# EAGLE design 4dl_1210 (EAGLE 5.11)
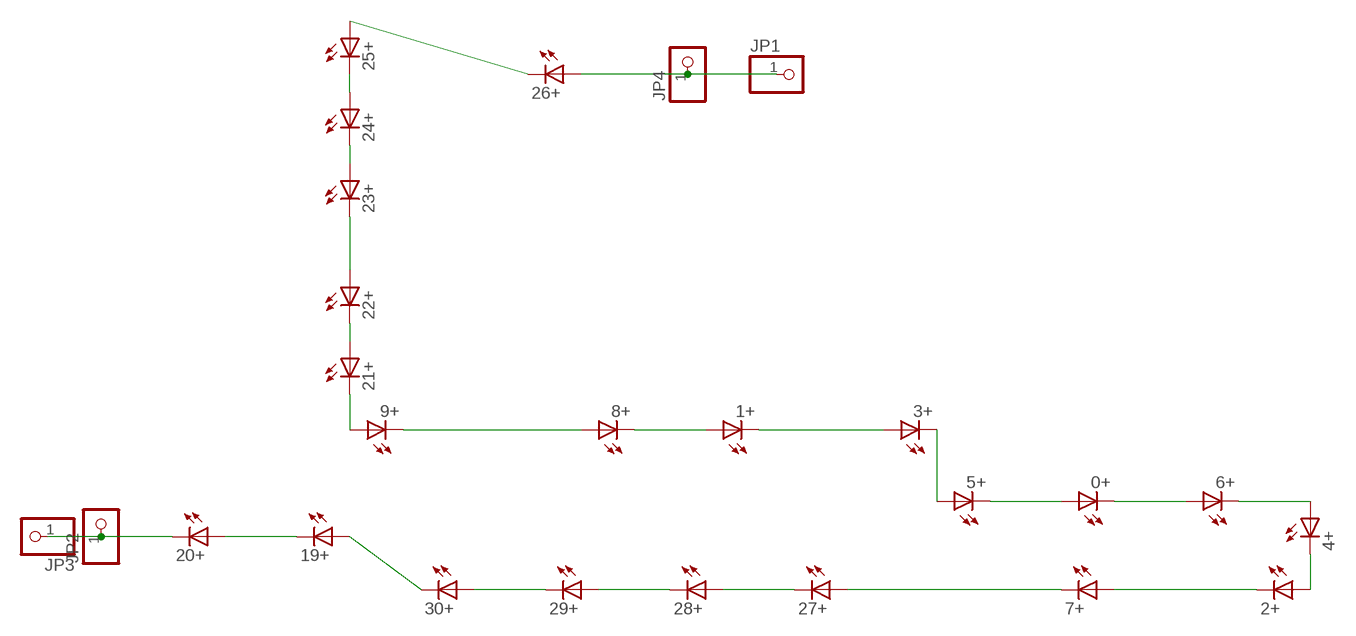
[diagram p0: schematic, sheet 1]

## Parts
0+  LED1210  [1210]
1+  LED1210  [1210]
2+  LED1210  [1210]
3+  LED1210  [1210]
4+  LED1210  [1210]
5+  LED1210  [1210]
6+  LED1210  [1210]
7+  LED1210  [1210]
8+  LED1210  [1210]
9+  LED1210  [1210]
19+  LED1210  [1210]
20+  LED1210  [1210]
21+  LED1210  [1210]
22+  LED1210  [1210]
23+  LED1210  [1210]
24+  LED1210  [1210]
25+  LED1210  [1210]
26+  LED1210  [1210]
27+  LED1210  [1210]
28+  LED1210  [1210]
29+  LED1210  [1210]
30+  LED1210  [1210]
JP1  PINHD-1X11MM6  [1X1MM8]
JP2  PINHD-1X11MM6  [1X1MM8]
JP3  PINHD-1X11X0.4  [1X01]
JP4  PINHD-1X11X0.4  [1X01]

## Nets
MINUS: 20+.P$2(C) JP2.1 JP3.1
N$2: 19+.P$2(C) 20+.P$1(A)
N$4: 19+.P$1(A) 30+.P$2(C)
N$6: 8+.P$1(A) 9+.P$2(C)
N$7: 29+.P$2(C) 30+.P$1(A)
N$8: 28+.P$2(C) 29+.P$1(A)
N$9: 27+.P$2(C) 28+.P$1(A)
N$12: 2+.P$2(C) 7+.P$1(A)
N$13: 7+.P$2(C) 27+.P$1(A)
N$14: 2+.P$1(A) 4+.P$2(C)
N$15: 4+.P$1(A) 6+.P$2(C)
N$16: 0+.P$2(C) 6+.P$1(A)
N$17: 0+.P$1(A) 5+.P$2(C)
N$18: 3+.P$2(C) 5+.P$1(A)
N$19: 1+.P$2(C) 3+.P$1(A)
N$20: 1+.P$1(A) 8+.P$2(C)
N$23: 9+.P$1(A) 21+.P$2(C)
N$24: 21+.P$1(A) 22+.P$2(C)
N$25: 22+.P$1(A) 23+.P$2(C)
N$26: 24+.P$1(A) 25+.P$2(C)
N$27: 25+.P$1(A) 26+.P$2(C)
N$28: 23+.P$1(A) 24+.P$2(C)
PLUS: 26+.P$1(A) JP1.1 JP4.1

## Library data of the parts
0+ 1+ 2+ 3+ 4+ 5+ 6+ 7+ 8+ 9+ 19+ 20+ 21+ 22+ 23+ 24+ 25+ 26+ 27+ 28+ 29+ 30+ = led(2):LED: LED
JP1-JP4 = pinhead:PINHD-1X1: PIN HEADER

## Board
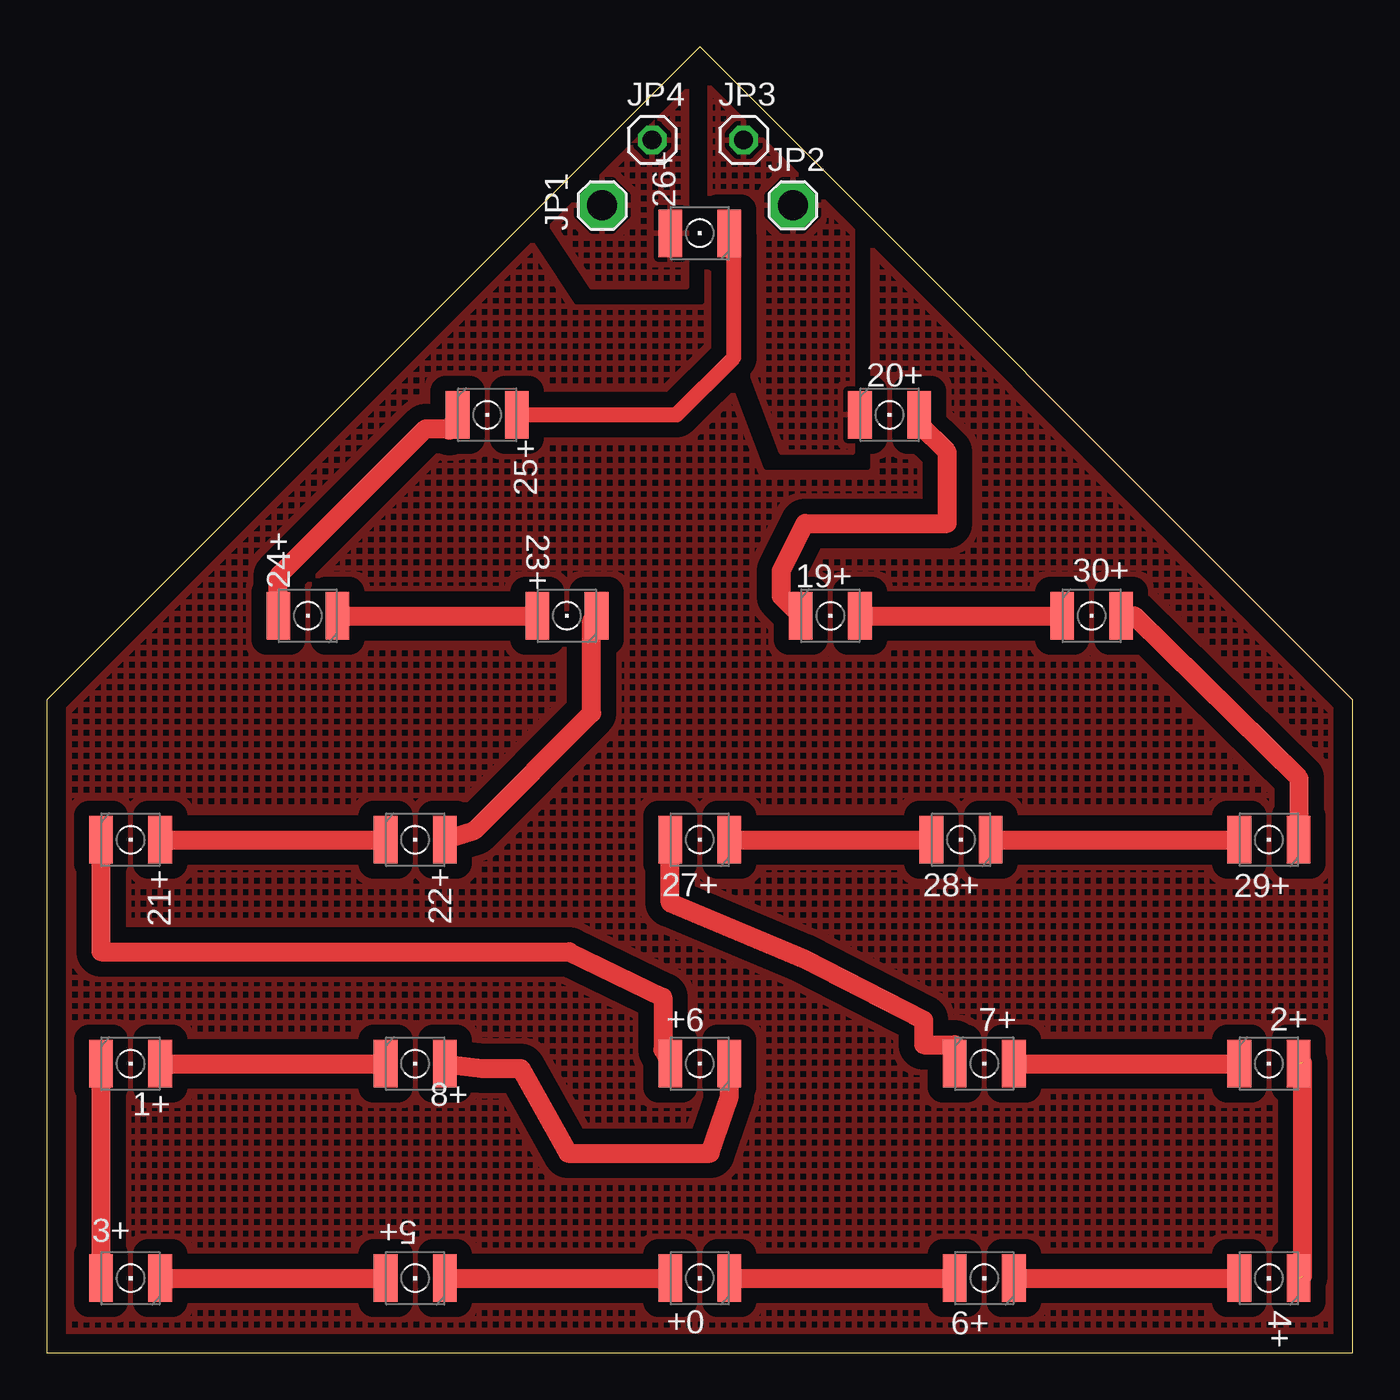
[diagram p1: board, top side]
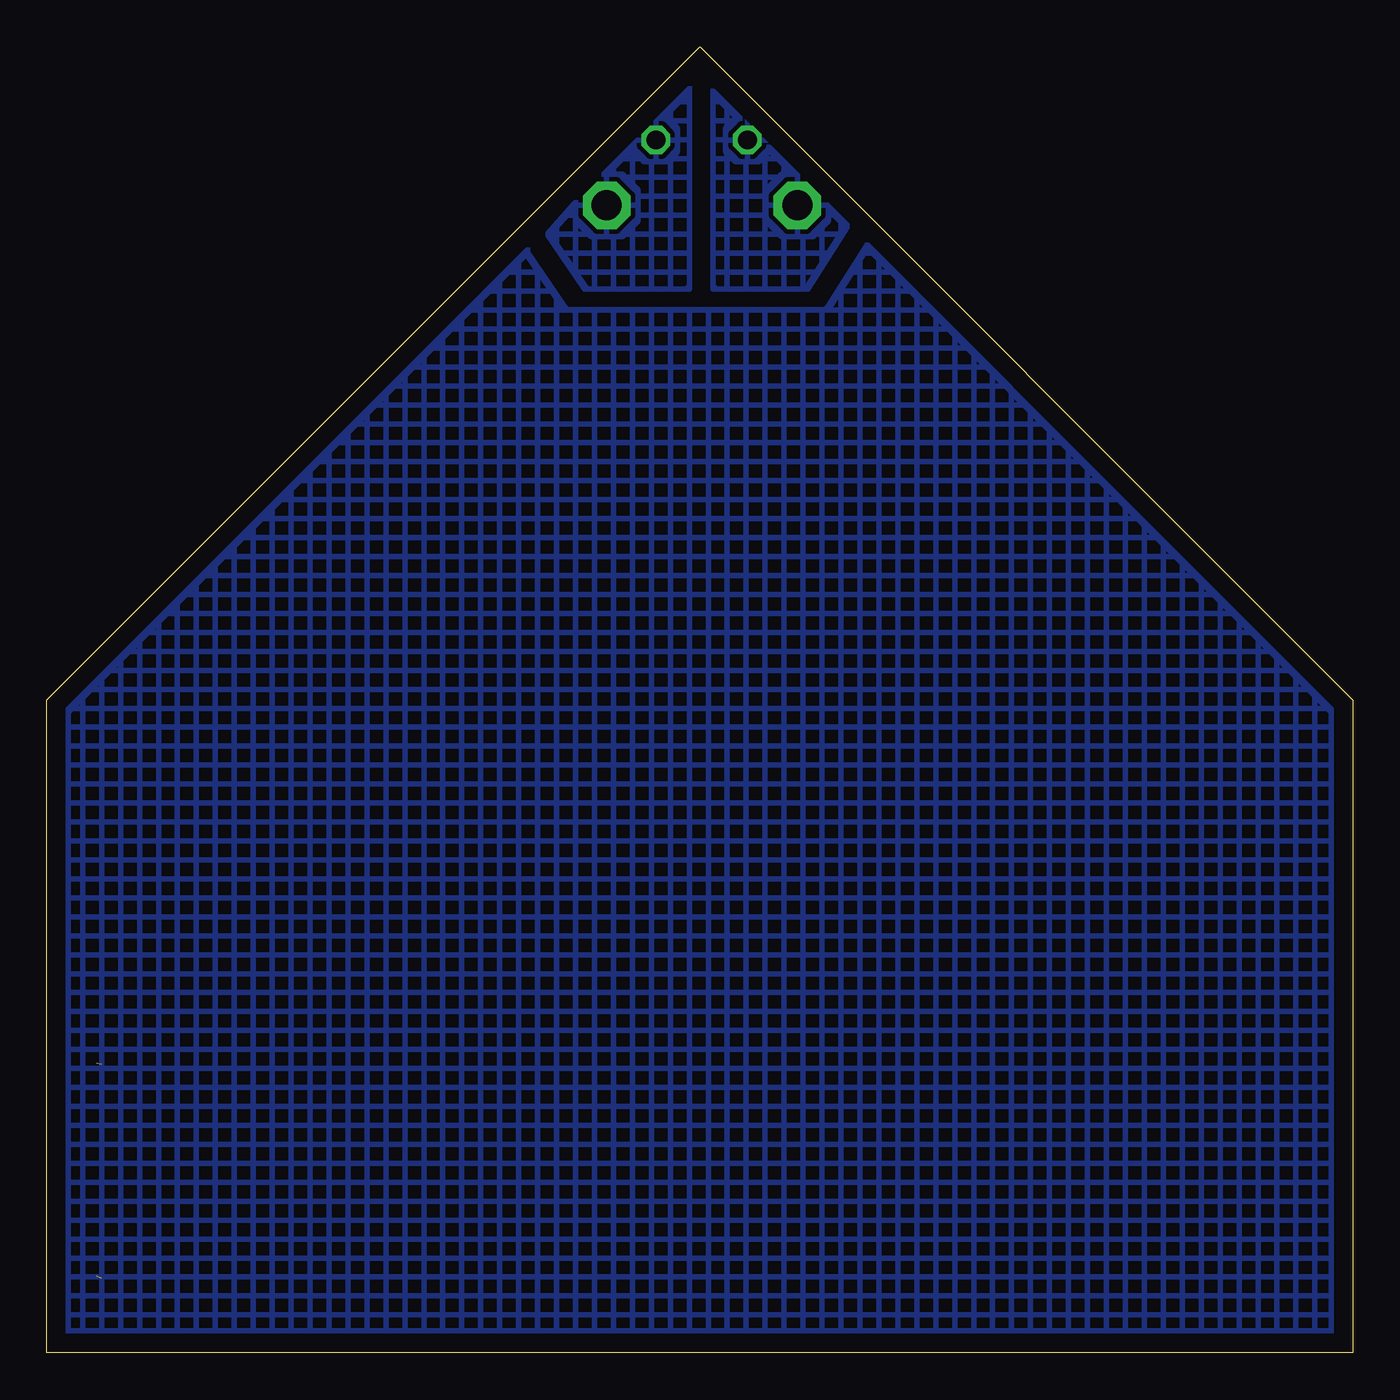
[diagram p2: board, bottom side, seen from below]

Size 70 x 70 mm. Coordinates in mm from the lower left corner, seen from the top.
Outline: 0,0 70,0 70,35 35,70 0,35 0,0
Copper layers (1*16): Top 0.035mm / dielectric 1.5mm / Bottom 0.035mm
Design rules "default": minimum track width 10mil, minimum drill 24mil, track to track 8mil, track to pad 8mil, pad to pad 8mil, via to via 8mil, smd to smd 8mil, copper to edge 40mil, drill to drill 8mil, minimum pad ring 10mil, minimum via ring 8mil, stop-mask expansion 4mil, vias tented up to drill 0mil, thermal gap 10mil

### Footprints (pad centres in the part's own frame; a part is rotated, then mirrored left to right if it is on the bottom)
1210 = smd 1.27 x 2.54: P$1 1.587,0; P$2 -1.587,0
1X1MM8 = drill 1.6 pad 2.54 octagon: 1 0,0
1X01 = drill 1.016 octagon: 1 0,0

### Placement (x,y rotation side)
0+  35,4 180 top
1+  4.5,15.5 0 top
2+  65.5,15.5 0 top
3+  4.5,4 180 top
4+  65.5,4 180 top
5+  19.75,4 180 top
6+  50.25,4 180 top
7+  50.25,15.5 0 top
8+  19.75,15.5 0 top
9+  35,15.5 180 top
19+  42,39.5 0 top
20+  45.17,50.27 0 top
21+  4.5,27.5 0 top
22+  19.75,27.5 0 top
23+  27.88,39.5 180 top
24+  14,39.5 180 top
25+  23.61,50.27 0 top
26+  35,60 180 top
27+  35,27.5 180 top
28+  49,27.5 180 top
29+  65.5,27.5 180 top
30+  56,39.5 0 top
JP1  29.77,61.5 90 top
JP2  39.99,61.5 0 top
JP3  37.35,65 0 top
JP4  32.45,65 0 top

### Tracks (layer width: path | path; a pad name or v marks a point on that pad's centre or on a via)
MINUS
  pour Top (isolate 0.813, hatched): 35.56,68.58 35.56,58.42 39.37,48.26 43.18,48.26 43.18,60.96
  pour Top (isolate 0.813, hatched): 35.56,68.58 35.56,58.42 39.37,48.26 43.18,48.26 43.18,60.96
  pour Bottom (isolate 0.813, hatched): 35.56,68.58 35.56,57 41.18,57 43.18,59.96
N$1
  pour Top (isolate 0.813, rank 3, hatched): 34.29,69.85 0,34.29 0,0 69.85,0 69.85,34.29
  pour Bottom (isolate 0.813, rank 3, hatched): 34.29,69.85 0,34.29 0,0 69.85,0 69.85,34.29
N$2
  Top 1.016: 20+.P$1 46.76,49.76 48.26,48.26 48.26,44.45 40.64,44.45 39.37,41.91 39.37,40.54 19+.P$2
N$4
  Top 1.016: 19+.P$1 30+.P$2
N$6
  Top 1.016: 9+.P$2 36.59,13.73 35.56,10.7 27.94,10.7 25.4,15.24 23.35,15.24 8+.P$1
N$7
  Top 1.016: 30+.P$1 58.29,39.5 67.12,30.78 67.12,28.52 29+.P$2
N$8
  Top 1.016: 28+.P$2 29+.P$1
N$9
  Top 1.016: 27+.P$2 28+.P$1
N$12
  Top 1.016: 7+.P$1 2+.P$2
N$13
  Top 1.016: 27+.P$1 33.41,24.13 40.56,21.13 46.99,17.84 46.99,16.51 48.65,16.51 7+.P$2
N$14  (2 unrouted)
  Top 1.016: 67.31,4.11 67.31,15.54
N$15
  Top 1.016: 6+.P$2 4+.P$1
N$16
  Top 1.016: 0+.P$2 6+.P$1
N$17
  Top 1.016: 5+.P$2 0+.P$1
N$18
  Top 1.016: 3+.P$2 5+.P$1
N$19
  Top 1.016: 3+.P$1 1+.P$2
N$20
  Top 1.016: 1+.P$1 8+.P$2
N$23
  Top 1.016: 21+.P$2 2.92,25.07 2.92,21.5 28,21.5 33.02,19.05 33.02,16.24 9+.P$1
N$24
  Top 1.016: 21+.P$1 22+.P$2
N$25
  Top 1.016: 22+.P$1 22.92,28 29.21,34.29 29.21,39.24 23+.P$2
N$26
  Top 1.016: 24+.P$1 12.41,41.62 20.32,49.53 21.59,49.53 21.59,49.43 25+.P$2
N$27
  Top 0.305: 36.83,59.76 26+.P$2
  Top 0.813: 25+.P$1 33.76,50.27 36.83,53.34 36.83,59.76
N$28
  Top 1.016: 24+.P$2 23+.P$1
PLUS
  pour Top (isolate 0.813, hatched): 34.29,68.58 34.29,57.15 29.21,57.15 26.67,60.96
  pour Bottom (isolate 0.813, hatched): 34.29,68.58 34.29,57 29.21,57 26.67,60.96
